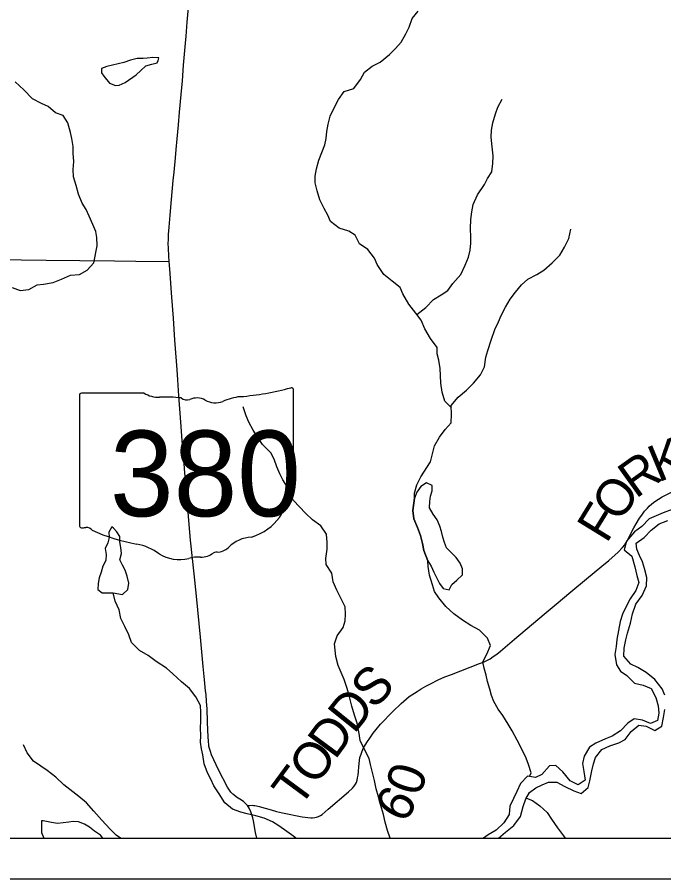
# Model space of a CAD drawing. Extents: x 0 to 34, y 0 to 22.
# Drawn here: x 5.21 to 6.205, y 13.563 to 14.889 of the extents above; entities that cross this region are included whole.
import ezdxf

# ---------------------------------------------------------------- set-up
doc = ezdxf.new("R2010")
doc.units = 0
for name, color, linetype in [('Default', 7, 'Continuous'), ('GM_X_Major_River', 7, 'Continuous'), ('GM_X_Minor_Lake', 7, 'Continuous'), ('GM_X_Minor_River', 7, 'Continuous'), ('GM_X_State_Location', 7, 'Continuous'), ('GM_X_State_Route', 7, 'Continuous'), ('GM_X_State_Shield', 7, 'Continuous'), ('GM_X_Township_Road', 7, 'Continuous'), ('GM_X_Township_Road_Text', 7, 'Continuous'), ('SH_Cut_Line', 7, 'Continuous'), ('SH_Data', 7, 'Continuous')]:
    doc.layers.add(name, color=color, linetype=linetype)

msp = doc.modelspace()

# ---------------------------------------------------------------- linework, layer by layer
at = {"layer": 'Default'}
msp.add_lwpolyline([(2.9696, 13.6252), (8.4279, 13.6252), (8.4024, 15.1386), (8.4023, 15.1576), (8.3761, 15.1587), (8.1234, 15.1688), (7.9465, 15.1727), (5.5157, 15.319), (4.819, 15.349), (4.2393, 15.3805), (4.2078, 15.3826), (3.1796, 15.4266), (3.1343, 15.4291), (3.0617, 14.6751), (3.0457, 14.4958), (3.0429, 14.4692)], close=True, dxfattribs=at)
at = {"layer": 'GM_X_Major_River'}
for points in [[(6.218, 14.1311), (6.2042, 14.1258), (6.1935, 14.1215), (6.1827, 14.1165), (6.1714, 14.1047), (6.1602, 14.097), (6.148, 14.0822), (6.1442, 14.069), (6.1561, 14.0592), (6.1609, 14.0431), (6.1636, 14.0294), (6.1667, 14.0187), (6.1625, 14.0063), (6.1534, 13.9936), (6.1474, 13.982), (6.1418, 13.9701), (6.1384, 13.9588), (6.1354, 13.9448), (6.1331, 13.9308), (6.132, 13.9203), (6.1298, 13.9082), (6.1324, 13.8922), (6.1389, 13.8825), (6.1486, 13.8754), (6.1603, 13.8637), (6.1735, 13.8607), (6.1859, 13.8554), (6.1931, 13.8419), (6.1965, 13.8289), (6.1977, 13.8179), (6.1954, 13.8062), (6.1851, 13.8015), (6.1724, 13.8068), (6.1595, 13.8087), (6.1499, 13.8025), (6.1386, 13.7907), (6.1258, 13.7823), (6.1158, 13.778), (6.1005, 13.7716), (6.0908, 13.7651), (6.0829, 13.7513), (6.0803, 13.74), (6.0822, 13.7278), (6.0841, 13.7144), (6.0737, 13.7075), (6.061, 13.7136), (6.05, 13.7275), (6.0393, 13.7369), (6.0294, 13.7364), (6.0177, 13.7235), (6.0077, 13.7184), (5.9953, 13.7207), (5.9847, 13.7096), (5.9791, 13.6972), (5.9738, 13.6864)], [(6.2068, 13.8453), (6.2029, 13.8553), (6.1916, 13.8693), (6.1782, 13.8803), (6.1652, 13.8878), (6.1547, 13.8931), (6.1437, 13.9055), (6.1445, 13.9176), (6.1467, 13.9305), (6.1493, 13.9406), (6.1539, 13.9561), (6.1573, 13.9704), (6.1623, 13.9854), (6.1718, 13.9988), (6.1786, 14.0138), (6.1794, 14.0267), (6.1756, 14.0405), (6.1725, 14.0504), (6.1679, 14.0604), (6.164, 14.07), (6.1627, 14.0795), (6.1751, 14.0879), (6.186, 14.0993), (6.1984, 14.1089), (6.2118, 14.1142)], [(5.951, 13.6252), (5.9617, 13.6347), (5.9745, 13.645), (5.9848, 13.6588), (5.989, 13.6738), (5.9931, 13.6858), (5.9987, 13.6955), (6.0084, 13.7029), (6.018, 13.7075), (6.0279, 13.7114), (6.0408, 13.7115), (6.0531, 13.705), (6.0666, 13.6982), (6.0782, 13.6941), (6.0887, 13.7033), (6.0913, 13.7135), (6.0947, 13.7289), (6.0969, 13.7395), (6.1002, 13.7493), (6.1097, 13.7615), (6.1224, 13.7676), (6.1361, 13.7722), (6.1461, 13.7772), (6.1552, 13.7895), (6.1668, 13.7994), (6.1781, 13.7976), (6.1916, 13.7911), (6.2024, 13.7977), (6.2051, 13.8112), (6.2069, 13.8233)], [(5.9738, 13.6864), (5.9682, 13.6744), (5.9674, 13.6615), (5.9591, 13.6488), (5.9474, 13.6378), (5.9347, 13.6305), (5.9277, 13.6252)]]:
    msp.add_lwpolyline(points, dxfattribs=at)
at = {"layer": 'GM_X_Minor_Lake'}
for points in [[(5.4266, 14.8224), (5.428, 14.8262), (5.4185, 14.8267), (5.4098, 14.8258), (5.4037, 14.8255), (5.3942, 14.8253), (5.3839, 14.8229), (5.3736, 14.8193), (5.3649, 14.8168), (5.3565, 14.8151), (5.3478, 14.813), (5.3393, 14.8097), (5.3392, 14.8033), (5.343, 14.7981)], [(5.343, 14.7981), (5.3518, 14.7875), (5.3608, 14.7839), (5.3665, 14.7841), (5.3757, 14.7881), (5.3926, 14.8003), (5.3999, 14.807), (5.4076, 14.814), (5.4168, 14.8165), (5.4252, 14.8186), (5.4266, 14.8224)], [(5.8421, 14.0519), (5.8473, 14.0439), (5.8513, 14.0347), (5.8553, 14.0266), (5.86, 14.0174), (5.8655, 14.0097), (5.875, 14.0073), (5.8789, 14.0155), (5.8866, 14.0222), (5.8955, 14.0308), (5.8953, 14.0399), (5.8917, 14.0487), (5.8855, 14.0575), (5.8784, 14.0645), (5.8706, 14.0719), (5.8677, 14.0803), (5.8652, 14.0883), (5.8628, 14.0974), (5.8607, 14.1054), (5.8563, 14.115), (5.8501, 14.1239), (5.8446, 14.1335), (5.8452, 14.1433), (5.8461, 14.1516), (5.8485, 14.1596), (5.8487, 14.1679), (5.8397, 14.1723), (5.8312, 14.1667), (5.825, 14.1578), (5.8214, 14.1487)], [(5.8214, 14.1487), (5.8191, 14.1298), (5.8204, 14.1165), (5.8262, 14.1035), (5.8308, 14.0912), (5.8336, 14.0787), (5.8357, 14.068), (5.8421, 14.0519)], [(5.3577, 14.1023), (5.3556, 14.1045), (5.3509, 14.0962), (5.3515, 14.0882), (5.349, 14.0799), (5.3451, 14.0713), (5.3468, 14.0621), (5.3462, 14.0527), (5.3415, 14.0437), (5.3387, 14.0346), (5.3358, 14.0259), (5.3341, 14.0172), (5.3336, 14.0081), (5.3407, 14.0027), (5.3486, 14.0029), (5.3573, 14.0027)], [(5.3573, 14.0027), (5.372, 14.0002), (5.3798, 14.008), (5.3815, 14.0178), (5.3791, 14.0285), (5.3758, 14.0377), (5.3718, 14.0453), (5.3678, 14.0538), (5.3703, 14.0632), (5.369, 14.0727), (5.3676, 14.0815), (5.3678, 14.0898), (5.363, 14.0967), (5.3577, 14.1023)], [(5.2496, 13.6518), (5.2471, 13.652), (5.2473, 13.6429), (5.2471, 13.6338), (5.2507, 13.6252)], [(5.3413, 13.6252), (5.338, 13.6298), (5.3286, 13.636), (5.3212, 13.6422), (5.3133, 13.6466), (5.3039, 13.6502), (5.2956, 13.6511), (5.2891, 13.6497), (5.2804, 13.6491), (5.2717, 13.6481), (5.2626, 13.6495), (5.2547, 13.6511), (5.2496, 13.6518)]]:
    msp.add_lwpolyline(points, dxfattribs=at)
at = {"layer": 'GM_X_Minor_River'}
for points in [[(5.8783, 14.2877), (5.868, 14.2977), (5.8638, 14.3118), (5.8618, 14.3255), (5.8613, 14.3376), (5.8611, 14.3479), (5.8591, 14.3608), (5.8566, 14.3707), (5.8561, 14.3806), (5.8461, 14.3941), (5.8373, 14.4091), (5.8315, 14.4225), (5.8234, 14.4332), (5.8127, 14.4471), (5.8036, 14.4628), (5.7992, 14.4728), (5.7873, 14.4825), (5.7743, 14.493), (5.764, 14.5084), (5.7596, 14.518), (5.7497, 14.5311), (5.7366, 14.5401), (5.73, 14.5535), (5.7203, 14.5597), (5.7056, 14.5642), (5.6922, 14.5743), (5.6882, 14.5839), (5.6824, 14.5942), (5.6758, 14.6077), (5.6716, 14.6214), (5.6684, 14.634), (5.6686, 14.6442), (5.6704, 14.6556), (5.674, 14.6688), (5.6788, 14.6804), (5.6832, 14.6925), (5.6853, 14.7023), (5.6867, 14.7129), (5.6884, 14.7243), (5.6917, 14.7367), (5.6981, 14.7506), (5.7044, 14.7619), (5.7133, 14.7746), (5.7278, 14.7792), (5.7384, 14.7931), (5.7443, 14.804), (5.7562, 14.8136), (5.7688, 14.8194), (5.7827, 14.8313), (5.7924, 14.8406), (5.8009, 14.8503), (5.808, 14.8634), (5.8131, 14.8735), (5.8179, 14.8867), (5.8273, 14.8983)], [(5.3325, 14.5496), (5.3308, 14.5591), (5.3261, 14.5698), (5.3203, 14.5828), (5.3156, 14.5928), (5.3097, 14.6028), (5.3039, 14.6162), (5.3004, 14.6299), (5.2965, 14.6429), (5.296, 14.6543), (5.297, 14.6668), (5.2958, 14.6797), (5.2956, 14.6896), (5.2936, 14.7021), (5.2915, 14.7116), (5.2876, 14.7261), (5.2803, 14.7373), (5.2686, 14.7417), (5.2575, 14.7514), (5.2469, 14.7558), (5.2334, 14.7633), (5.2197, 14.7768), (5.2067, 14.7892)], [(5.825, 14.4312), (5.8388, 14.442), (5.8508, 14.4543), (5.8626, 14.4613), (5.8726, 14.4683), (5.8804, 14.4788), (5.8928, 14.4929), (5.8996, 14.5072), (5.9048, 14.5193), (5.9073, 14.5302), (5.9082, 14.5408), (5.908, 14.5503), (5.9079, 14.5636), (5.9082, 14.5776), (5.9096, 14.5894), (5.9117, 14.6003), (5.9185, 14.6154), (5.9294, 14.6311), (5.9341, 14.6408), (5.9404, 14.651), (5.9422, 14.6634), (5.9424, 14.6756), (5.9412, 14.6893), (5.9396, 14.7041), (5.9398, 14.7147), (5.9423, 14.726), (5.9464, 14.74), (5.95, 14.7502), (5.9567, 14.7629)], [(5.9984, 13.7201), (6.0011, 13.7259), (5.9968, 13.7385), (5.9936, 13.7484), (5.9866, 13.7622), (5.9793, 13.776), (5.9717, 13.7906), (5.9655, 13.8006), (5.9574, 13.814), (5.9504, 13.8237), (5.9434, 13.8356), (5.9398, 13.8451), (5.9374, 13.8546), (5.9338, 13.8665), (5.9318, 13.8764), (5.9286, 13.8867), (5.9265, 13.8966), (5.9328, 13.9086), (5.9384, 13.9218), (5.9337, 13.9333), (5.9214, 13.9456), (5.9083, 13.9524), (5.8952, 13.961), (5.8818, 13.9703), (5.8699, 13.9816), (5.8588, 13.9951), (5.8522, 14.0051), (5.849, 14.015), (5.8447, 14.0299), (5.8423, 14.0432), (5.8421, 14.0519), (5.8357, 14.068), (5.8336, 14.0787), (5.8308, 14.0912), (5.8262, 14.1035), (5.8204, 14.1165), (5.8191, 14.1298), (5.8214, 14.1487), (5.8212, 14.1563), (5.8248, 14.1691), (5.8312, 14.1812), (5.846, 14.2044), (5.8493, 14.2168), (5.8522, 14.2289), (5.8601, 14.2424), (5.8686, 14.254), (5.8779, 14.2645), (5.8786, 14.2781), (5.8781, 14.2914), (5.8886, 14.3041), (5.9017, 14.3148), (5.9122, 14.3256), (5.923, 14.3383), (5.929, 14.3507), (5.9315, 14.3655), (5.9344, 14.3756), (5.9393, 14.3919), (5.9453, 14.4084), (5.9508, 14.4197), (5.9548, 14.4299), (5.9615, 14.4426), (5.9686, 14.455), (5.9768, 14.4655), (5.9861, 14.4767), (5.9961, 14.4856), (6.0099, 14.4929), (6.0207, 14.4995), (6.0334, 14.511), (6.0454, 14.5225), (6.0525, 14.5349), (6.0592, 14.5481), (6.0621, 14.5624)], [(5.2021, 14.4729), (5.2141, 14.4681), (5.2278, 14.4697), (5.2405, 14.4767), (5.2503, 14.478), (5.2648, 14.4804), (5.2778, 14.4858), (5.2915, 14.492), (5.3056, 14.4928), (5.3175, 14.4994), (5.3276, 14.511), (5.3326, 14.5367), (5.3325, 14.5496)], [(5.7838, 13.6252), (5.7799, 13.6373), (5.7763, 13.6499), (5.7736, 13.6617), (5.7689, 13.677), (5.7658, 13.6888), (5.7626, 13.701), (5.7599, 13.714), (5.7564, 13.7285), (5.7535, 13.7384), (5.7518, 13.7479), (5.7449, 13.7606), (5.738, 13.7755), (5.7363, 13.7865), (5.7332, 13.8022), (5.7293, 13.8144), (5.7251, 13.8285), (5.7212, 13.8426), (5.718, 13.8556), (5.713, 13.8697), (5.7087, 13.8804), (5.704, 13.8911), (5.7005, 13.9049), (5.6995, 13.9144), (5.6982, 13.9243), (5.7023, 13.9367), (5.7116, 13.9494), (5.7145, 13.96), (5.7154, 13.9698), (5.7149, 13.9812), (5.7083, 13.9935), (5.7018, 14.0069), (5.6964, 14.0199), (5.6944, 14.0332), (5.6856, 14.0463), (5.685, 14.0558), (5.6872, 14.0702), (5.687, 14.0804), (5.6858, 14.0934), (5.6773, 14.106), (5.6646, 14.115), (5.6535, 14.1255), (5.6442, 14.1352), (5.6353, 14.1452), (5.6302, 14.1548), (5.6259, 14.1655), (5.6185, 14.1766), (5.6142, 14.1862), (5.6095, 14.1969), (5.6055, 14.2084), (5.6004, 14.2184), (5.5874, 14.2311), (5.5793, 14.2434), (5.5731, 14.2531), (5.5665, 14.2657), (5.5622, 14.2753), (5.5575, 14.289)], [(5.6387, 13.6252), (5.6357, 13.6276), (5.6249, 13.6355), (5.6126, 13.644), (5.6028, 13.6503), (5.5901, 13.6559), (5.5769, 13.6599), (5.5637, 13.6628), (5.5539, 13.6653), (5.5411, 13.6701), (5.5296, 13.6798), (5.5207, 13.6933), (5.5123, 13.706), (5.508, 13.7163), (5.5028, 13.7259), (5.4978, 13.7397), (5.4954, 13.7534), (5.4934, 13.7629), (5.4921, 13.7728), (5.4923, 13.7826), (5.4921, 13.7952), (5.4923, 13.8054), (5.4922, 13.8191), (5.4917, 13.8297), (5.4848, 13.8427), (5.4752, 13.8555), (5.4629, 13.8659), (5.4491, 13.878), (5.4394, 13.8869), (5.4234, 13.8971), (5.4111, 13.9064), (5.398, 13.9143), (5.3857, 13.9263), (5.3814, 13.9381), (5.3756, 13.9512), (5.3694, 13.9634), (5.3666, 13.9768), (5.3605, 13.9898), (5.3573, 14.0027)], [(5.3689, 13.6252), (5.3618, 13.6297), (5.3529, 13.6393), (5.34, 13.6532), (5.3274, 13.6668), (5.3166, 13.6799), (5.3043, 13.6892), (5.2909, 13.7001), (5.2812, 13.7075), (5.2689, 13.7192), (5.2559, 13.7293), (5.2458, 13.7359), (5.2346, 13.7437), (5.225, 13.7565), (5.2192, 13.7687)], [(5.9937, 13.6868), (6.0032, 13.683), (6.0144, 13.6752), (6.0256, 13.6647), (6.0322, 13.6547), (6.0418, 13.6412), (6.051, 13.6289), (6.0537, 13.6252)]]:
    msp.add_lwpolyline(points, dxfattribs=at)
at = {"layer": 'GM_X_State_Route'}
msp.add_lwpolyline([(5.5785, 13.6252), (5.5767, 13.6341), (5.5734, 13.6518), (5.5724, 13.6567), (5.5711, 13.6614), (5.5693, 13.6659), (5.5666, 13.6716), (5.5641, 13.6756), (5.5622, 13.6778), (5.56, 13.6799), (5.5579, 13.6817), (5.5524, 13.6852), (5.5475, 13.6884), (5.5433, 13.6918), (5.5416, 13.6932), (5.5388, 13.6961), (5.5367, 13.6992), (5.5336, 13.7037), (5.5198, 13.7302), (5.509, 13.7537), (5.5072, 13.7585), (5.5058, 13.7633), (5.5049, 13.7667), (5.5046, 13.7687), (5.5041, 13.7739), (5.5038, 13.7819), (5.5034, 13.7914), (5.5029, 13.8044), (5.502, 13.8242), (5.5012, 13.8357), (5.5004, 13.8466), (5.4998, 13.8521), (5.4981, 13.8692), (5.4961, 13.8895), (5.4918, 13.9344), (5.4855, 13.9976), (5.482, 14.032), (5.4767, 14.084), (5.4717, 14.1386), (5.4702, 14.1555), (5.4672, 14.1943), (5.466, 14.2098), (5.4639, 14.2367), (5.4621, 14.259), (5.4601, 14.2863), (5.4587, 14.306), (5.4569, 14.3308), (5.4558, 14.3462), (5.4548, 14.3592), (5.4525, 14.3919), (5.4501, 14.4254), (5.4479, 14.458), (5.4469, 14.4719), (5.4458, 14.4871), (5.4448, 14.5009), (5.4439, 14.5126), (5.4433, 14.5212), (5.4424, 14.5331), (5.4423, 14.5403), (5.4424, 14.5467), (5.4427, 14.5543), (5.4435, 14.5658), (5.4453, 14.584), (5.4475, 14.6083), (5.45, 14.6375), (5.4513, 14.6504), (5.4534, 14.6726), (5.4545, 14.685), (5.456, 14.7017), (5.4579, 14.7231), (5.4598, 14.7429), (5.4621, 14.7696), (5.464, 14.7908), (5.4659, 14.8152), (5.4688, 14.8489), (5.4697, 14.8597), (5.4716, 14.8814), (5.4735, 14.9038)], dxfattribs=at)
at = {"layer": 'GM_X_State_Shield'}
for p, q in [((5.4052, 14.3101), (5.3087, 14.3101)), ((5.635, 14.2104), (5.635, 14.3151)), ((5.3054, 14.3067), (5.3054, 14.1066)), ((5.635, 14.2104), (5.635, 14.2104))]:
    msp.add_line(p, q, dxfattribs=at)
for centre, major_axis, start_param, end_param in [((5.3092, 14.3071), (0.00382, 0), 1.712693, 3.28349), ((5.4282, 14.3334), (0.037, 0), 4.042523, 4.731795), ((5.5176, 14.583), (0.3495, 0), 4.814394, 5.042369), ((5.6314, 14.3155), (0.00367, 0), 6.141152, 7.989035), ((5.4405, 14.1978), (0.133, 0), 1.404758, 1.657858), ((5.4707, 14.3082), (0.0107, 0), 3.836095, 5.185415), ((5.4863, 14.285), (0.0222, 0), 0.950623, 2.079405), ((5.515, 14.3168), (0.0267, 0), 4.081561, 5.145723), ((5.5622, 14.249), (0.0703, 0), 1.699011, 2.107814), ((5.6342, 14.2027), (0.00568, 0), 1.883978, 3.671073), ((5.6311, 14.21), (0.00393, 0), 5.05454, 6.418171), ((5.5981, 14.1895), (0.0341, 0), 5.934695, 6.695948), ((5.6482, 14.1666), (0.0248, 0), 2.387724, 3.262537), ((5.5372, 14.1533), (0.0874, 0), 5.101752, 6.440018), ((5.3093, 14.1061), (0.00385, 0), 3.00124, 4.508301), ((5.3098, 14.1266), (0.0294, 0), 4.665946, 4.897461), ((5.3159, 14.095), (0.0106, 0), 0.519207, 1.627899), ((5.4497, 14.2748), (0.2524, 0), 4.195997, 4.488961), ((5.5741, 14.0504), (0.0479, 0), 1.647645, 2.488434), ((5.3744, 14.0167), (0.079, 0), 0.823519, 1.323587), ((5.5134, 14.0872), (0.0282, 0), 4.937069, 5.64225), ((5.4598, 14.094), (0.0501, 0), 4.026481, 4.996735), ((5.4888, 14.0249), (0.0412, 0), 1.495662, 1.94098), ((5.4925, 14.0791), (0.0267, 0), 4.691044, 5.507374), ((5.5166, 14.0597), (0.00752, 0), 1.147584, 2.315152)]:
    msp.add_ellipse(centre, major_axis=major_axis, ratio=0.8, start_param=start_param, end_param=end_param, dxfattribs=at)
at = {"layer": 'GM_X_Township_Road'}
for points in [[(4.8363, 14.5184), (4.8444, 14.5185), (4.8739, 14.5189), (4.8996, 14.5193), (4.9254, 14.5194), (4.9561, 14.5193), (4.9908, 14.5187), (5.0099, 14.5185), (5.027, 14.5183), (5.0466, 14.5182), (5.0646, 14.518), (5.0833, 14.5177), (5.1087, 14.5171), (5.1242, 14.5167), (5.1404, 14.5164), (5.254, 14.5151), (5.3062, 14.5144), (5.3596, 14.5137), (5.3923, 14.5133), (5.4439, 14.5126)], [(5.5641, 13.6756), (5.5677, 13.6757), (5.5715, 13.6759), (5.5735, 13.6757), (5.5746, 13.6757), (5.5758, 13.6755), (5.578, 13.6751), (5.5825, 13.674), (5.6005, 13.6688), (5.6089, 13.6662), (5.618, 13.6641), (5.6485, 13.6583), (5.6616, 13.6566), (5.6645, 13.6566), (5.668, 13.657), (5.6707, 13.6575), (5.6736, 13.6584), (5.6765, 13.66), (5.6791, 13.6617), (5.6886, 13.6698), (5.7197, 13.6966), (5.7261, 13.7023), (5.7286, 13.7051), (5.7307, 13.7084), (5.7321, 13.7111), (5.7331, 13.7143), (5.7339, 13.718), (5.7346, 13.7222), (5.7353, 13.7278), (5.7355, 13.7353), (5.7366, 13.745), (5.7375, 13.7492), (5.7391, 13.7545), (5.7409, 13.7591), (5.7431, 13.7641), (5.7456, 13.7686), (5.749, 13.7742), (5.7525, 13.7794), (5.7578, 13.7869), (5.7623, 13.7924), (5.7692, 13.8007), (5.7881, 13.8204), (5.8007, 13.8323), (5.8132, 13.8431), (5.8256, 13.8509), (5.8319, 13.8549), (5.8388, 13.8591), (5.846, 13.863), (5.8578, 13.869), (5.8683, 13.8735), (5.8782, 13.8773), (5.9217, 13.894), (5.9278, 13.8963), (5.9338, 13.8992), (5.9378, 13.9015), (5.9425, 13.9048), (5.9482, 13.9087), (5.9539, 13.9129), (5.9755, 13.9317), (6.0212, 13.97), (6.0398, 13.9855), (6.0622, 14.0042), (6.0865, 14.0245), (6.11, 14.0441), (6.1207, 14.0525), (6.1353, 14.0652), (6.142, 14.0727), (6.1451, 14.0765), (6.1483, 14.0819), (6.1594, 14.1029), (6.1628, 14.1092), (6.1681, 14.1179), (6.1714, 14.1226), (6.1757, 14.1284), (6.1802, 14.1333), (6.1828, 14.136), (6.1868, 14.1397), (6.1917, 14.1435), (6.1972, 14.1471), (6.2027, 14.1504), (6.2183, 14.1582)]]:
    msp.add_lwpolyline(points, dxfattribs=at)
at = {"layer": 'SH_Cut_Line'}
msp.add_lwpolyline([(2.9696, 13.6252), (9.0621, 13.6252), (9.0621, 20.4252), (3.5682, 20.4252), (3.5424, 20.1754), (3.5231, 19.8516), (3.5169, 19.7823), (3.5125, 19.7343), (3.5092, 19.6961), (3.5066, 19.6647), (3.4966, 19.5464), (3.4903, 19.4759), (3.4748, 19.2963), (3.47, 19.2407), (3.2768, 17.1355), (3.2667, 16.919), (3.1974, 16.1596), (3.1343, 15.4291), (3.0617, 14.6751), (3.0457, 14.4958), (3.0429, 14.4692)], close=True, dxfattribs=at)
at = {"layer": 'SH_Data'}
msp.add_line((2.1704, 13.5628), (9.1704, 13.5628), dxfattribs=at)

# ---------------------------------------------------------------- texts
at = {"layer": 'GM_X_State_Location'}
for s in ['s', 'r']:
    msp.add_text(s, height=0.000189, dxfattribs=at).set_placement((5.4665, 14.1933))
msp.add_text('380', height=0.000189, rotation=0, dxfattribs=at).set_placement((5.3997, 14.1796))
at = {"layer": 'GM_X_State_Shield'}
msp.add_text('380', height=0.13184, dxfattribs=at).set_placement((5.3524, 14.1207))
at = {"layer": 'GM_X_Township_Road_Text'}
for s, rotation, p in [('K', 22.5502, (6.197, 14.1724)), ('R', 35.6205, (6.162, 14.1468)), ('O', 54.8964, (6.1368, 14.1095)), ('F', 58.4691, (6.1173, 14.0776)), ('S', 45.1428, (5.7585, 13.8221)), ('D', 51.2443, (5.7283, 13.7843)), ('D', 53.6357, (5.699, 13.7445)), ('O', 53.6386, (5.6694, 13.7043)), ('T', 53.6392, (5.6442, 13.6701)), ('0', 71.6808, (5.8294, 13.6881)), ('6', 59.6252, (5.8063, 13.646))]:
    msp.add_text(s, height=0.0568, rotation=rotation, dxfattribs=at).set_placement(p)

doc.saveas('drawing.dxf')
